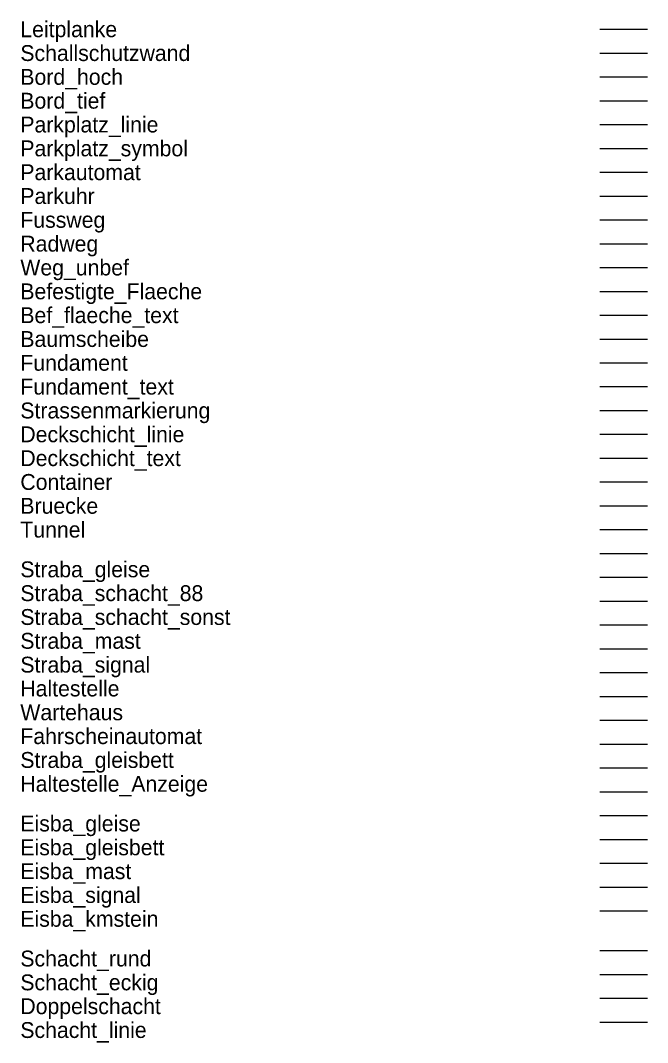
# Model space of a CAD drawing. Extents: x 0 to 177, y -135 to 1.
# Drawn here: x 43.5 to 83, y -63.8 to 0.6 of the extents above; entities that cross this region are included whole.
import ezdxf

# ---------------------------------------------------------------- set-up
doc = ezdxf.new("R2010")
doc.units = 0
for name, color, linetype in [('Acker', 7, 'Continuous'), ('Baum_text', 7, 'Continuous'), ('Baumscheibe', 7, 'Continuous'), ('Bef_flaeche_text', 7, 'Continuous'), ('Befestigte_Flaeche', 7, 'Continuous'), ('Boeschung_bef', 7, 'Continuous'), ('Boeschung_ok', 7, 'Continuous'), ('Boeschung_uk', 7, 'Continuous'), ('Boeschung_unbef', 7, 'Continuous'), ('Bord_hoch', 7, 'Continuous'), ('Bord_tief', 7, 'Continuous'), ('Bruecke', 7, 'Continuous'), ('Busch_platz', 7, 'Continuous'), ('Busch_verm', 7, 'Continuous'), ('Container', 7, 'Continuous'), ('Deckschicht_linie', 7, 'Continuous'), ('Deckschicht_text', 7, 'Continuous'), ('Doppelschacht', 7, 'Continuous'), ('Durchlass', 7, 'Continuous'), ('Eisba_gleisbett', 7, 'Continuous'), ('Eisba_gleise', 7, 'Continuous'), ('Eisba_kmstein', 7, 'Continuous'), ('Eisba_mast', 7, 'Continuous'), ('Eisba_signal', 7, 'Continuous'), ('Fahrscheinautomat', 7, 'Continuous'), ('Felsen', 7, 'Continuous'), ('Felsen_linie', 7, 'Continuous'), ('Fliessrichtung', 7, 'Continuous'), ('Friedhof', 7, 'Continuous'), ('Fundament', 7, 'Continuous'), ('Fundament_text', 7, 'Continuous'), ('Fussweg', 7, 'Continuous'), ('Garten', 7, 'Continuous'), ('Gebuesch', 7, 'Continuous'), ('Gewaessername', 7, 'Continuous'), ('Graben', 7, 'Continuous'), ('Gruenanlage', 7, 'Continuous'), ('Haltestelle', 7, 'Continuous'), ('Haltestelle_Anzeige', 7, 'Continuous'), ('Hecke', 7, 'Continuous'), ('Kabel_elektro', 7, 'Continuous'), ('Kronendurch_linie', 7, 'Continuous'), ('Laubbaum', 7, 'Continuous'), ('Laubwald', 7, 'Continuous'), ('Leitplanke', 7, 'Continuous'), ('Mauer_frei', 7, 'Continuous'), ('Mauer_stuetz', 7, 'Continuous'), ('Mischwald', 7, 'Continuous'), ('Nadelbaum', 7, 'Continuous'), ('Nadelwald', 7, 'Continuous'), ('Nutzgrenz', 7, 'Continuous'), ('Oedland', 7, 'Continuous'), ('Palisade_beton', 7, 'Continuous'), ('Palisade_holz', 7, 'Continuous'), ('Parkautomat', 7, 'Continuous'), ('Parkplatz_linie', 7, 'Continuous'), ('Parkplatz_symbol', 7, 'Continuous'), ('Parkuhr', 7, 'Continuous'), ('Pegel', 7, 'Continuous'), ('Pergola', 7, 'Continuous'), ('Quelle', 7, 'Continuous'), ('Radweg', 7, 'Continuous'), ('Schacht_eckig', 7, 'Continuous'), ('Schacht_linie', 7, 'Continuous'), ('Schacht_rund', 7, 'Continuous'), ('Schallschutzwand', 7, 'Continuous'), ('Schutzrohr_elektro', 7, 'Continuous'), ('Spundwand', 7, 'Continuous'), ('Straba_gleisbett', 7, 'Continuous'), ('Straba_gleise', 7, 'Continuous'), ('Straba_mast', 7, 'Continuous'), ('Straba_schacht_88', 7, 'Continuous'), ('Straba_schacht_sonst', 7, 'Continuous'), ('Straba_signal', 7, 'Continuous'), ('Strassenmarkierung', 7, 'Continuous'), ('Text_kabel_elektro', 7, 'Continuous'), ('Text_schutzrohr_elektro', 7, 'Continuous'), ('Tunnel', 7, 'Continuous'), ('Uferlinie', 7, 'Continuous'), ('Wartehaus', 7, 'Continuous'), ('Weg_unbef', 7, 'Continuous'), ('Wehr', 7, 'Continuous'), ('Wiese', 7, 'Continuous')]:
    doc.layers.add(name, color=color, linetype=linetype)

msp = doc.modelspace()

# ---------------------------------------------------------------- linework, layer by layer
at = {"layer": 'Acker'}
msp.add_line((80, -34.5), (83, -34.5), dxfattribs=at)
at = {"layer": 'Baum_text'}
msp.add_line((80, -55.5), (83, -55.5), dxfattribs=at)
at = {"layer": 'Boeschung_bef'}
msp.add_line((80, -7.5), (83, -7.5), dxfattribs=at)
at = {"layer": 'Boeschung_ok'}
msp.add_line((80, -9), (83, -9), dxfattribs=at)
at = {"layer": 'Boeschung_uk'}
msp.add_line((80, -10.5), (83, -10.5), dxfattribs=at)
at = {"layer": 'Boeschung_unbef'}
msp.add_line((80, -12), (83, -12), dxfattribs=at)
at = {"layer": 'Busch_platz'}
msp.add_line((80, -49.5), (83, -49.5), dxfattribs=at)
at = {"layer": 'Busch_verm'}
msp.add_line((80, -48), (83, -48), dxfattribs=at)
at = {"layer": 'Durchlass'}
msp.add_line((80, -22.5), (83, -22.5), dxfattribs=at)
at = {"layer": 'Felsen'}
msp.add_line((80, -27), (83, -27), dxfattribs=at)
at = {"layer": 'Felsen_linie'}
msp.add_line((80, -28.5), (83, -28.5), dxfattribs=at)
at = {"layer": 'Fliessrichtung'}
msp.add_line((80, -16.5), (83, -16.5), dxfattribs=at)
at = {"layer": 'Friedhof'}
msp.add_line((80, -37.5), (83, -37.5), dxfattribs=at)
at = {"layer": 'Garten'}
msp.add_line((80, -30), (83, -30), dxfattribs=at)
at = {"layer": 'Gebuesch'}
msp.add_line((80, -39), (83, -39), dxfattribs=at)
at = {"layer": 'Gewaessername'}
msp.add_line((80, -13.5), (83, -13.5), dxfattribs=at)
at = {"layer": 'Graben'}
msp.add_line((80, -21), (83, -21), dxfattribs=at)
at = {"layer": 'Gruenanlage'}
msp.add_line((80, -33), (83, -33), dxfattribs=at)
at = {"layer": 'Hecke'}
msp.add_line((80, -52.5), (83, -52.5), dxfattribs=at)
at = {"layer": 'Kabel_elektro'}
msp.add_line((80, -58), (83, -58), dxfattribs=at)
at = {"layer": 'Kronendurch_linie'}
msp.add_line((80, -54), (83, -54), dxfattribs=at)
at = {"layer": 'Laubbaum'}
msp.add_line((80, -45), (83, -45), dxfattribs=at)
at = {"layer": 'Laubwald'}
msp.add_line((80, -40.5), (83, -40.5), dxfattribs=at)
at = {"layer": 'Mauer_frei'}
msp.add_line((80, -4.5), (83, -4.5), dxfattribs=at)
at = {"layer": 'Mauer_stuetz'}
msp.add_line((80, -6), (83, -6), dxfattribs=at)
at = {"layer": 'Mischwald'}
msp.add_line((80, -43.5), (83, -43.5), dxfattribs=at)
at = {"layer": 'Nadelbaum'}
msp.add_line((80, -46.5), (83, -46.5), dxfattribs=at)
at = {"layer": 'Nadelwald'}
msp.add_line((80, -42), (83, -42), dxfattribs=at)
at = {"layer": 'Nutzgrenz'}
msp.add_line((80, -51), (83, -51), dxfattribs=at)
at = {"layer": 'Oedland'}
msp.add_line((80, -36), (83, -36), dxfattribs=at)
at = {"layer": 'Palisade_beton'}
msp.add_line((80, 0), (83, 0), dxfattribs=at)
at = {"layer": 'Palisade_holz'}
msp.add_line((80, -1.5), (83, -1.5), dxfattribs=at)
at = {"layer": 'Pegel'}
msp.add_line((80, -24), (83, -24), dxfattribs=at)
at = {"layer": 'Pergola'}
msp.add_line((80, -3), (83, -3), dxfattribs=at)
at = {"layer": 'Quelle'}
msp.add_line((80, -19.5), (83, -19.5), dxfattribs=at)
at = {"layer": 'Schutzrohr_elektro'}
msp.add_line((80, -61), (83, -61), dxfattribs=at)
at = {"layer": 'Spundwand'}
msp.add_line((80, -18), (83, -18), dxfattribs=at)
at = {"layer": 'Text_kabel_elektro'}
msp.add_line((80, -59.5), (83, -59.5), dxfattribs=at)
at = {"layer": 'Text_schutzrohr_elektro'}
msp.add_line((80, -62.5), (83, -62.5), dxfattribs=at)
at = {"layer": 'Uferlinie'}
msp.add_line((80, -15), (83, -15), dxfattribs=at)
at = {"layer": 'Wehr'}
msp.add_line((80, -25.5), (83, -25.5), dxfattribs=at)
at = {"layer": 'Wiese'}
msp.add_line((80, -31.5), (83, -31.5), dxfattribs=at)

# ---------------------------------------------------------------- texts
at = {"layer": 'Baumscheibe'}
msp.add_text('Baumscheibe', height=1, dxfattribs=at).set_placement((43.5, -20))
at = {"layer": 'Bef_flaeche_text'}
msp.add_text('Bef_flaeche_text', height=1, dxfattribs=at).set_placement((43.5, -18.5))
at = {"layer": 'Befestigte_Flaeche'}
msp.add_text('Befestigte_Flaeche', height=1, dxfattribs=at).set_placement((43.5, -17))
at = {"layer": 'Bord_hoch'}
msp.add_text('Bord_hoch', height=1, dxfattribs=at).set_placement((43.5, -3.5))
at = {"layer": 'Bord_tief'}
msp.add_text('Bord_tief', height=1, dxfattribs=at).set_placement((43.5, -5))
at = {"layer": 'Bruecke'}
msp.add_text('Bruecke', height=1, dxfattribs=at).set_placement((43.5, -30.5))
at = {"layer": 'Container'}
msp.add_text('Container', height=1, dxfattribs=at).set_placement((43.5, -29))
at = {"layer": 'Deckschicht_linie'}
msp.add_text('Deckschicht_linie', height=1, dxfattribs=at).set_placement((43.5, -26))
at = {"layer": 'Deckschicht_text'}
msp.add_text('Deckschicht_text', height=1, dxfattribs=at).set_placement((43.5, -27.5))
at = {"layer": 'Doppelschacht'}
msp.add_text('Doppelschacht', height=1, dxfattribs=at).set_placement((43.5, -62))
at = {"layer": 'Eisba_gleisbett'}
msp.add_text('Eisba_gleisbett', height=1, dxfattribs=at).set_placement((43.5, -52))
at = {"layer": 'Eisba_gleise'}
msp.add_text('Eisba_gleise', height=1, dxfattribs=at).set_placement((43.5, -50.5))
at = {"layer": 'Eisba_kmstein'}
msp.add_text('Eisba_kmstein', height=1, dxfattribs=at).set_placement((43.5, -56.5))
at = {"layer": 'Eisba_mast'}
msp.add_text('Eisba_mast', height=1, dxfattribs=at).set_placement((43.5, -53.5))
at = {"layer": 'Eisba_signal'}
msp.add_text('Eisba_signal', height=1, dxfattribs=at).set_placement((43.5, -55))
at = {"layer": 'Fahrscheinautomat'}
msp.add_text('Fahrscheinautomat', height=1, dxfattribs=at).set_placement((43.5, -45))
at = {"layer": 'Fundament'}
msp.add_text('Fundament', height=1, dxfattribs=at).set_placement((43.5, -21.5))
at = {"layer": 'Fundament_text'}
msp.add_text('Fundament_text', height=1, dxfattribs=at).set_placement((43.5, -23))
at = {"layer": 'Fussweg'}
msp.add_text('Fussweg', height=1, dxfattribs=at).set_placement((43.5, -12.5))
at = {"layer": 'Haltestelle'}
msp.add_text('Haltestelle', height=1, dxfattribs=at).set_placement((43.5, -42))
at = {"layer": 'Haltestelle_Anzeige'}
msp.add_text('Haltestelle_Anzeige', height=1, dxfattribs=at).set_placement((43.5, -48))
at = {"layer": 'Leitplanke'}
msp.add_text('Leitplanke', height=1, dxfattribs=at).set_placement((43.5, -0.5))
at = {"layer": 'Parkautomat'}
msp.add_text('Parkautomat', height=1, dxfattribs=at).set_placement((43.5, -9.5))
at = {"layer": 'Parkplatz_linie'}
msp.add_text('Parkplatz_linie', height=1, dxfattribs=at).set_placement((43.5, -6.5))
at = {"layer": 'Parkplatz_symbol'}
msp.add_text('Parkplatz_symbol', height=1, dxfattribs=at).set_placement((43.5, -8))
at = {"layer": 'Parkuhr'}
msp.add_text('Parkuhr', height=1, dxfattribs=at).set_placement((43.5, -11))
at = {"layer": 'Radweg'}
msp.add_text('Radweg', height=1, dxfattribs=at).set_placement((43.5, -14))
at = {"layer": 'Schacht_eckig'}
msp.add_text('Schacht_eckig', height=1, dxfattribs=at).set_placement((43.5, -60.5))
at = {"layer": 'Schacht_linie'}
msp.add_text('Schacht_linie', height=1, dxfattribs=at).set_placement((43.5, -63.5))
at = {"layer": 'Schacht_rund'}
msp.add_text('Schacht_rund', height=1, dxfattribs=at).set_placement((43.5, -59))
at = {"layer": 'Schallschutzwand'}
msp.add_text('Schallschutzwand', height=1, dxfattribs=at).set_placement((43.5, -2))
at = {"layer": 'Straba_gleisbett'}
msp.add_text('Straba_gleisbett', height=1, dxfattribs=at).set_placement((43.5, -46.5))
at = {"layer": 'Straba_gleise'}
msp.add_text('Straba_gleise', height=1, dxfattribs=at).set_placement((43.5, -34.5))
at = {"layer": 'Straba_mast'}
msp.add_text('Straba_mast', height=1, dxfattribs=at).set_placement((43.5, -39))
at = {"layer": 'Straba_schacht_88'}
msp.add_text('Straba_schacht_88', height=1, dxfattribs=at).set_placement((43.5, -36))
at = {"layer": 'Straba_schacht_sonst'}
msp.add_text('Straba_schacht_sonst', height=1, dxfattribs=at).set_placement((43.5, -37.5))
at = {"layer": 'Straba_signal'}
msp.add_text('Straba_signal', height=1, dxfattribs=at).set_placement((43.5, -40.5))
at = {"layer": 'Strassenmarkierung'}
msp.add_text('Strassenmarkierung', height=1, dxfattribs=at).set_placement((43.5, -24.5))
at = {"layer": 'Tunnel'}
msp.add_text('Tunnel', height=1, dxfattribs=at).set_placement((43.5, -32))
at = {"layer": 'Wartehaus'}
msp.add_text('Wartehaus', height=1, dxfattribs=at).set_placement((43.5, -43.5))
at = {"layer": 'Weg_unbef'}
msp.add_text('Weg_unbef', height=1, dxfattribs=at).set_placement((43.5, -15.5))

doc.saveas('drawing.dxf')
